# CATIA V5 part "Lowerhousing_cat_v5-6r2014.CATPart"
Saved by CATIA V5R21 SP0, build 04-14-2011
Part number: Lowerhousing
Bounding box of the stored display mesh (mm): x -190.5 to 190.5, y -101.6 to 101.6, z -165.1 to 0
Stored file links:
  D:\CATIA V5R21 E-RESOURCES\CATIA-V5R21\catia-v5r21-Tut\c12-catia-v5r21-tut\c12-catia-v5r21-tut01\Lowerhousing_cat_v5r21.CATPart
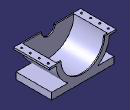
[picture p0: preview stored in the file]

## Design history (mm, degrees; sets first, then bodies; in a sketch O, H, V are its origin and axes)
Body1 (main body)
  Sketch1 on zx-plane, origin (0, 0, 0), H (-1, 0, 0), V (0, 0, 1)
    line L1 (-190.5, 0) -> (190.5, 0)
    point P1 (-190.5, 0)
    arc A1 centre (0, 0) radius 152.4 from (-152.0438, -10.414) to (-84.2423, -127) ccw
    line L2 (-190.5, -10.414) -> (-152.0438, -10.414)
    line L3 (-177.8, -165.1) -> (177.8, -165.1)
    point P6 (177.8, -165.1)
    line L4 (-177.8, -127) -> (-84.2423, -127)
    line L5 (177.8, -165.1) -> (177.8, -127)
    line L6 (-177.8, -165.1) -> (-177.8, -127)
    arc A2 centre (0, 0) radius 152.4 from (84.2423, -127) to (152.0438, -10.414) ccw
    point P10 (84.2423, -127)
    line L7 (84.2423, -127) -> (177.8, -127)
    line L8 (190.5, -10.414) -> (190.5, 0)
    line L9 (-190.5, -10.414) -> (-190.5, 0)
    point P11 (152.0438, -10.414)
    line L10 (152.0438, -10.414) -> (190.5, -10.414)
    length L1 = 381
    distance P1 V = 190.5
    radius A1 = 152.4
    distance L2 L1 = 10.414
    distance L3 H = 165.1
    distance L4 L3 = 38.1
    distance P6 V = 177.8
    length L3 = 355.6
    coincidence: P1 H, L4 P10, A1 A2, L4 L7, L2 P11, L2 L10
    horizontal: L1 H, L2 H, L3 H, L4 H, L7 H, L10 H
    vertical: L6 V, L5 V, L8 V, L9 V
  Pad1: profile Sketch1, direction (0, 1, 0), length 101.6, mirrored extent
  Sketch2 on face of Pad1, origin (0, 0, 0), H (1, 0, 0), V (0, 1, 0)
    circle A1 centre (-171.45, 76.2) radius 5.207
    point P1 (-171.45, 76.2)
    reference projected line E1 (-190.5, 101.6) -> (190.5, 101.6) from edge of Pad1
    reference projected line E2 (-190.5, -101.6) -> (-190.5, 101.6) from edge of Pad1
    radius A1 = 5.207
    distance E1 P1 = 25.4
    distance E2 P1 = 19.05
  Pocket1: profile Sketch2, direction (0, 0, -1), through (limit type 6)
  RectPattern1: of Pocket1, direction 1 instances 4, spacing 50.8, along edge of Pad1 reversed, direction 2 instances 2, spacing 342.9, along edge of Pad1 reversed
  Sketch3 on face of Pad1, origin (0, 0, 0), H (1, 0, 0), V (0, 1, 0)
    point P1 (0, -95.25)
    line L1 (0, -95.25) -> (146.05, -95.25)
    line L2 (146.05, -95.25) -> (146.05, 95.25)
    line L3 (146.05, 95.25) -> (0, 95.25)
    line L4 (0, 95.25) -> (0, -95.25)
    reference projected line E1 (-190.5, -101.6) -> (190.5, -101.6) from edge of Pad1
    reference projected line E2 (190.5, 101.6) -> (-190.5, 101.6) from edge of Pad1
    distance E1 L1 = 6.35
    length L3 = 146.05
    distance E2 L3 = 6.35
    coincidence: P1 V
    horizontal: L1 H, L3 H
    vertical: L2 V, L4 V
  Groove1: profile Sketch3, axis edge of Sketch3, angle 360
  Sketch4 on face of Pad1, origin (0, 101.6, 0), H (-1, 0, 0), V (0, 0, 1)
    circle A1 centre (0, 0) radius 38.1
    circle A2 centre (0, 0) radius 123.825
    radius A2 = 123.825
    radius A1 = 38.1
  MultiPocket1: profile Sketch4, domains (length 25.4; length 279.4)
